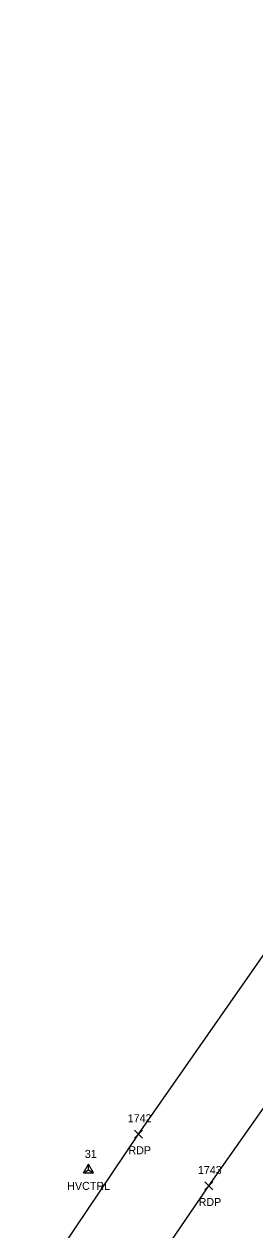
# Model space of a CAD drawing. Extents: x 1508122 to 1515053, y 865012 to 875267.
# Drawn here: x 1511383.6 to 1511441.4, y 870102.7 to 870404.1 of the extents above; entities that cross this region are included whole.
import ezdxf

# ---------------------------------------------------------------- set-up
doc = ezdxf.new("R2010")
doc.units = 0
for name, color, linetype in [('C_A', 7, 'Continuous'), ('C_I', 7, 'Continuous'), ('CPSM', 7, 'Continuous'), ('P_A', 7, 'Continuous'), ('P_I', 7, 'Continuous'), ('P_TIC', 7, 'Continuous'), ('PET', 7, 'Continuous')]:
    doc.layers.add(name, color=color, linetype=linetype)

msp = doc.modelspace()

# ---------------------------------------------------------------- linework, layer by layer
at = {"layer": 'CPSM'}
for p, q in [((1511398.48, 870116.93), (1511399.73, 870119.1)), ((1511400.98, 870116.93), (1511399.73, 870119.1)), ((1511399.73, 870117.65), (1511399.73, 870119.1)), ((1511398.48, 870116.93), (1511399.73, 870117.65)), ((1511398.48, 870116.93), (1511400.98, 870116.93)), ((1511399.73, 870117.65), (1511399.73, 870117.65)), ((1511399.73, 870117.65), (1511400.98, 870116.93))]:
    msp.add_line(p, q, dxfattribs=at)
at = {"layer": 'P_TIC'}
for points in [[(1511411.26, 870125.56), (1511413.26, 870127.56)], [(1511413.26, 870125.56), (1511411.26, 870127.56)], [(1511428.85, 870112.63), (1511430.85, 870114.63)], [(1511430.85, 870112.63), (1511428.85, 870114.63)]]:
    msp.add_lwpolyline(points, dxfattribs=at)
at = {"layer": 'PET'}
for points in [[(1511383.61, 870084.12), (1511412.26, 870126.56), (1511452.57, 870184.22), (1511495.01, 870243.9), (1511536.43, 870301.66), (1511577.25, 870358.31), (1511604.57, 870395.61), (1511633.77, 870437), (1511660.33, 870476.14), (1511693.36, 870526.39), (1511725.02, 870575.36), (1511757.6, 870625.52), (1511818.4, 870716.85), (1511845.17, 870758.16), (1511876.46, 870805.52)], [(1511401.8, 870072.69), (1511429.85, 870113.63), (1511470.29, 870171.01), (1511511.87, 870230.12), (1511553.79, 870288.68), (1511595.89, 870346.86), (1511627.03, 870388.71), (1511652.98, 870425.11), (1511678.36, 870464.06), (1511711.38, 870514.06), (1511744.84, 870564.55), (1511778.97, 870616.56), (1511830.16, 870695.92), (1511863.87, 870746.26), (1511895.07, 870793.96)]]:
    msp.add_lwpolyline(points, dxfattribs=at)

# ---------------------------------------------------------------- texts
at = {"layer": 'C_A'}
msp.add_text('HVCTRL', height=2, dxfattribs=at).set_placement((1511394.42, 870112.65))
at = {"layer": 'C_I'}
msp.add_text('31', height=2, dxfattribs=at).set_placement((1511398.83, 870120.65))
at = {"layer": 'P_A'}
for p in [(1511409.75, 870121.56), (1511427.34, 870108.63)]:
    msp.add_text('RDP', height=2, dxfattribs=at).set_placement(p)
at = {"layer": 'P_I'}
for s, p in [('1742', (1511409.57, 870129.56)), ('1743', (1511427.16, 870116.63))]:
    msp.add_text(s, height=2, dxfattribs=at).set_placement(p)

doc.saveas('drawing.dxf')
